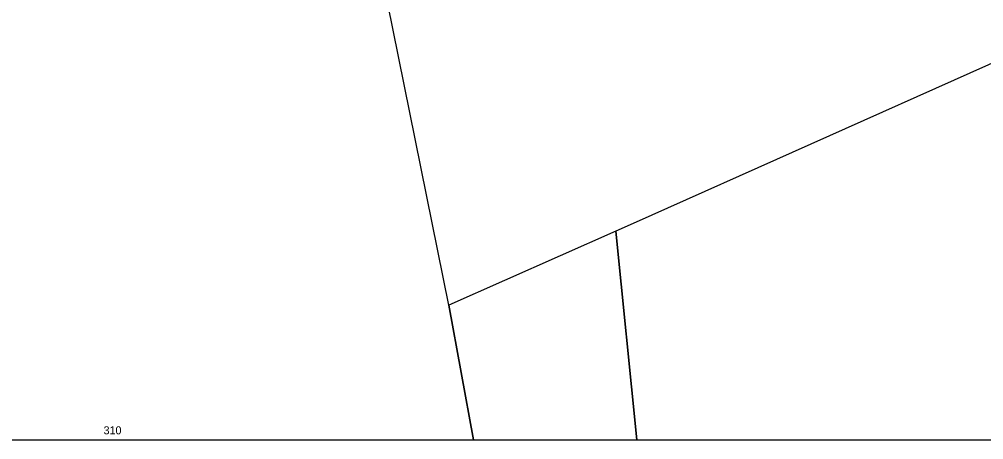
# Model space of a CAD drawing. Extents: x -873642 to -872917, y -1012962 to -1012567.
# Drawn here: x -873481.3 to -873378.9, y -1012961.7 to -1012917 of the extents above; entities that cross this region are included whole.
import ezdxf

# ---------------------------------------------------------------- set-up
doc = ezdxf.new("R2010")
doc.units = 0
doc.layers.add('cisla_parcelni_kn', color=7, linetype='Continuous')
doc.layers.add('parcely_kn', color=7, linetype='Continuous')

msp = doc.modelspace()

# ---------------------------------------------------------------- linework, layer by layer
at = {"layer": 'parcely_kn'}
for p, q in [((-873505.02, -1012961.69), (-873433.11, -1012961.69)), ((-873505.02, -1012961.69), (-873433.11, -1012961.69)), ((-873433.11, -1012961.69), (-873415.75, -1012961.69)), ((-873433.11, -1012961.69), (-873415.75, -1012961.69)), ((-873415.75, -1012961.69), (-873304.73, -1012961.69)), ((-873415.75, -1012961.69), (-873304.73, -1012961.69))]:
    msp.add_line(p, q, dxfattribs=at)
for points in [[(-873149.77, -1012848.73), (-873202.95, -1012863.9), (-873307.96, -1012890.45), (-873318.36, -1012895.27), (-873328.54, -1012899.56), (-873340.69, -1012904.93), (-873416.15, -1012938.7), (-873417.98, -1012939.52), (-873435.72, -1012947.37), (-873445.76, -1012897.62), (-873478.14, -1012904.47), (-873481.91, -1012884.93)], [(-873149.77, -1012848.73), (-873202.95, -1012863.9), (-873307.96, -1012890.45), (-873318.36, -1012895.27), (-873328.54, -1012899.56), (-873340.69, -1012904.93), (-873416.15, -1012938.7), (-873417.98, -1012939.52), (-873435.72, -1012947.37), (-873445.76, -1012897.62), (-873478.14, -1012904.47), (-873481.91, -1012884.93)], [(-873433.11, -1012961.69), (-873435.72, -1012947.37), (-873445.76, -1012897.62), (-873478.14, -1012904.47), (-873481.91, -1012884.93), (-873488.8, -1012886.1), (-873510.5, -1012890.72), (-873518.4, -1012892.32), (-873514.15, -1012917.38), (-873512.63, -1012922.93), (-873511.15, -1012929.54), (-873509.89, -1012935.71), (-873508.05, -1012945.66), (-873505.9, -1012956.95), (-873505.02, -1012961.69)], [(-873433.11, -1012961.69), (-873435.72, -1012947.37), (-873445.76, -1012897.62), (-873478.14, -1012904.47), (-873481.91, -1012884.93), (-873488.8, -1012886.1), (-873510.5, -1012890.72), (-873518.4, -1012892.32), (-873514.15, -1012917.38), (-873512.63, -1012922.93), (-873511.15, -1012929.54), (-873509.89, -1012935.71), (-873508.05, -1012945.66), (-873505.9, -1012956.95), (-873505.02, -1012961.69)], [(-873304.73, -1012961.69), (-873311.77, -1012944.32), (-873318.35, -1012932.75), (-873322.43, -1012911.49), (-873328.54, -1012899.56), (-873340.69, -1012904.93), (-873416.15, -1012938.7), (-873417.98, -1012939.52), (-873415.75, -1012961.69)], [(-873304.73, -1012961.69), (-873311.77, -1012944.32), (-873318.35, -1012932.75), (-873322.43, -1012911.49), (-873328.54, -1012899.56), (-873340.69, -1012904.93), (-873416.15, -1012938.7), (-873417.98, -1012939.52), (-873415.75, -1012961.69)], [(-873415.75, -1012961.69), (-873417.98, -1012939.52), (-873435.72, -1012947.37), (-873433.11, -1012961.69)], [(-873415.75, -1012961.69), (-873417.98, -1012939.52), (-873435.72, -1012947.37), (-873433.11, -1012961.69)]]:
    msp.add_lwpolyline(points, dxfattribs=at)

# ---------------------------------------------------------------- texts
at = {"layer": 'cisla_parcelni_kn'}
msp.add_text('310', height=0.85, dxfattribs=at).set_placement((-873472.38, -1012961.11))
msp.add_text('310', height=0.85, dxfattribs=at).set_placement((-873472.38, -1012961.11))

doc.saveas('drawing.dxf')
